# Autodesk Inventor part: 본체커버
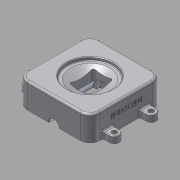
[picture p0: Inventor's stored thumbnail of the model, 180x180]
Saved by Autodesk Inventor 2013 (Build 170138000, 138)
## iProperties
Created: 2018-01
Part Number: 본체커버
Material: 알루미늄 6061
Document SubType Name: Modeling
Designer: mduedu
Density: 1 g/cm^3
Author: mduedu
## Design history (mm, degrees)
sketch "스케치1"
  geometry: L1 (55, 55)-(-55, 55); L2 (-55, 55)-(-55, -55); L3 (-55, -55)-(55, -55); L4 (55, -55)-(55, 55); L5 (55, 55)-(-55, -55); L6 (-55, 55)-(55, -55); 1 further point
  constraints: 12 end point, 2 midpoint, 2 parallel, 1 horizontal, 1 perpendicular
  dimensions: "d0" = 110 distance of L3.end L2.end; "d1" = 110 distance of L2.end L1.end
extrude "돌출1" new body sketch "스케치1" distance "d2" = 38; taper "d3" = 0 deg
sketch "스케치2"
  geometry: L1 (-55, 55)-(55, 55) reference; L2 (-55, -55)-(-55, 55) reference; L3 (55, -55)-(-55, -55) reference; L4 (55, 55)-(55, -55) reference; L5 (0, 55)-(7.5, 55); L6 (7.5, 55)-(7.5, 36); L7 (7.5, 36)-(0, 36); L8 (0, 36)-(0, 55); L9 (0, 36)-(16, 36); L10 (16, 36)-(16, 22); L11 (16, 22)-(0, 22); L12 (0, 22)-(0, 36); L13 (0, 22)-(20, 22); L14 (20, 22)-(20, -25); L15 (20, -25)-(0, -25); L16 (0, -25)-(0, 22); L17 (0, -25)-(15, -25); L18 (15, -25)-(15, -30); L19 (15, -30)-(0, -30); L20 (0, -30)-(0, -25); 1 further point
  constraints: 32 end point, 8 parallel, 4 horizontal, 4 perpendicular, 1 midpoint
  dimensions: "d4" = 15 diameter of L6 L8; "d6" = 32 diameter of L10 L12; "d7" = 40 diameter of L14 L16; "d8" = 30 diameter of L18 L20; "d9" = 5 distance of L17.end L18.end; "d10" = 47 distance of L13.end L14.end; "d11" = 14 distance of L9.end L10.end; "d12" = 19 distance of L5.end L6.end
revolve "회전1" sketch "스케치2" stored, may be unused: angle "d13" = 90 deg
fillet "모깎기1" dims "d14" = 1
fillet "모깎기2" dims "d15" = 15
fillet "모깎기3" dims "d16" = 3
sketch "스케치3"
  geometry: L1 (-15, -17)-(15, -17); L2 (15, -17)-(15, 20); L3 (15, 20)-(-15, 20); L4 (-15, 20)-(-15, -17); L5 (-19, -22)-(19, -22) reference; L6 (19, 25)-(-19, 25) reference; 2 further points
  constraints: 8 end point, 2 parallel, 1 horizontal, 1 midpoint, 1 perpendicular, 1 vertical alignment
  dimensions: "d17" = 5 distance between parallel lines of L1 L5; "d18" = 5 distance between parallel lines of L6 L3; "d19" = 37 distance of L3.end L1.start (derived); "d20" = 30 distance between parallel lines of L2 L4
extrude "돌출2" cut sketch "스케치3" stored distance "d21" = 38; taper "d22" = 0 deg
fillet "모깎기4" dims "d23" = 3
sketch "스케치4"
  geometry: L1 (38, 35)-(33, 35); L2 (33, 35)-(33, 30); L3 (33, 30)-(26, 15); L4 (26, 15)-(26, 0); L5 (26, 0)-(38, 0); L6 (38, 0)-(38, 35); L7 (38, 40)-(38, -40) reference; 1 further point
  constraints: 12 end point, 2 parallel, 1 collinear, 1 horizontal, 1 horizontal alignment, 1 perpendicular
  dimensions: "d24" = 5 distance of L1.start L1.end; "d26" = 70 diameter of L1 L5; "d28" = 60 diameter of L2.end L5; "d29" = 30 diameter of L3.end L5; "d30" = 7 horizontal distance of L2.end L3.end
revolve "회전2" sketch "스케치4" stored, may be unused: angle "d31" = 90 deg
chamfer "모따기1" distance "d32" = 1; stored, may be unused: second distance "d33" = 2, angle "d34" = 45 deg
fillet "모깎기5" dims "d35" = 1
chamfer "모따기2" distance "d36" = 1; stored, may be unused: second distance "d37" = 2, angle "d38" = 45 deg
sketch "스케치5"
  geometry: L1 (7.5, 54)-(8.5, 55) reference; L2 (7.5, 54)-(7.5, 37) reference; L3 (8.5, 36)-(7.5, 37) reference; L4 (8.5, 36)-(15, 36) reference; L5 (16, 35)-(16, 22) reference; L6 (16, 22)-(19, 22) reference; L7 (20, 21)-(20, -24) reference; L8 (19, -25)-(15, -25) reference; L9 (15, -25)-(15, -29) reference; L10 (14, -30)-(-14, -30) reference; L11 (-15, -29)-(-15, -25) reference; L12 (-15, -25)-(-19, -25) reference; L13 (-20, -24)-(-20, 21) reference; L14 (-19, 22)-(-16, 22) reference; L15 (-16, 22)-(-16, 35) reference; L16 (-15, 36)-(-8.5, 36) reference; L17 (-7.5, 37)-(-8.5, 36) reference; L18 (-7.5, 37)-(-7.5, 54) reference; L19 (-8.5, 55)-(-7.5, 54) reference; L20 (-40, 55)-(-8.5, 55) reference; L21 (-55, -40)-(-55, 40) reference; L22 (40, -55)-(-40, -55) reference; L23 (55, 40)-(55, -40) reference; L24 (8.5, 55)-(40, 55) reference; L25 (55, 35.5)-(65, 35.5); L26 (65, 20.5)-(55, 20.5); L27 (55, 20.5)-(55, 35.5); L28 (55, 40)-(55, -40) reference; A1 r 1 centre (15, 35) between (16, 35) and (15, 36) reference; A2 r 1 centre (19, 21) between (20, 21) and (19, 22) reference; A3 r 1 centre (19, -24) between (19, -25) and (20, -24) reference; A4 r 1 centre (14, -29) between (14, -30) and (15, -29) reference; A5 r 1 centre (-14, -29) between (-15, -29) and (-14, -30) reference; A6 r 1 centre (-19, -24) between (-20, -24) and (-19, -25) reference; A7 r 1 centre (-19, 21) between (-19, 22) and (-20, 21) reference; A8 r 1 centre (-15, 35) between (-15, 36) and (-16, 35) reference; A9 r 15 centre (-40, 40) between (-40, 55) and (-55, 40) reference; A10 r 15 centre (-40, -40) between (-55, -40) and (-40, -55) reference; A11 r 15 centre (40, -40) between (40, -55) and (55, -40) reference; A12 r 15 centre (40, 40) between (55, 40) and (40, 55) reference; A13 r 7.5 centre (65, 28) between (65, 20.5) and (65, 35.5); 1 further point
  constraints: 6 end point, 2 point on circle, 2 tangent, 1 centre point, 1 collinear, 1 horizontal, 1 parallel, 1 point on line
  dimensions: "d39" = 15 distance between parallel lines of L26 L25; "d41" = 28 vertical distance of A13.centre point (0, 0); "d42" = 10 distance from line of A13.centre L23
extrude "돌출3" join sketch "스케치5" distance "d43" = 10; taper "d44" = 0 deg
fillet "모깎기6" dims "d45" = 1
fillet "모깎기7" dims "d46" = 3
sketch "스케치6"
  geometry: A1 r 7.5 centre (-65, 28) between (-65, 35.5) and (-65, 20.5) reference; A2 r 7.5 centre (-65, -28) between (-65, -20.5) and (-65, -35.5) reference; A3 r 7.5 centre (65, -28) between (65, -35.5) and (65, -20.5) reference; A4 r 7.5 centre (65, 28) between (65, 20.5) and (65, 35.5) reference; 5 further points
  constraints: 4 coincident
sketch "스케치7"
  geometry: 4 further points
  constraints: 4 other
hole "구멍1" sketch "스케치7" at (-65, 28), (65, 28), (-65, -28), (65, -28) diameter "d47" = 4.5; stored, may be unused: countersink angle "d51" = 90 deg, drill point angle "d53" = 0 deg; dims "d48" = 6, "d49" = 8, "d50" = 4.6, "d52" = 8
sketch "스케치8"
  geometry: L1 (-95, 35)-(-95, 0) reference; L2 (0, 38)-(-80, 38) reference; 2 further points
  constraints: 1 other
  dimensions: "d54" = 55 distance from line of point (-40, 23) L1; "d55" = 15 distance from line of point (-40, 23) L2
feature "엠보싱1" sketch "스케치8" dims "d0" = 110, "d1" = 110, "d56" = 0.5, "d57" = 0
node "솔리드1"
mirror "대칭1"
mirror "대칭2"
node "투영된 루프1"
node "투영된 루프2"
